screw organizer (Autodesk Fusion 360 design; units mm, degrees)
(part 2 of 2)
sketch "Sketch7" plane through (0, 0, 5) normal (0, 0, 1) x axis (-1, 0, 0)
  line L1 (-684.5, 175) -> (-500, 175)
  line L2 (-684.5, -75) -> (-684.5, 175)
  line L3 (-500, -75) -> (-684.5, -75)
  line L4 (-500, 175) -> (-500, -75)
  line L5 (-505, -70) -> (-679.5, -70)
  line L6 (-505, 170) -> (-505, -70)
  line L7 (-679.5, 170) -> (-505, 170)
  line L8 (-555.4, -70) -> (-505, -70)
  line L9 (-555.4, -38.6) -> (-555.4, -70)
  line L10 (-505, -38.6) -> (-555.4, -38.6)
  line L11 (-505, -70) -> (-505, -38.6)
  line L12 (-560.4, -70) -> (-555.4, -70)
  line L13 (-560.4, 170) -> (-560.4, -70)
  line L14 (-555.4, 170) -> (-560.4, 170)
  line L15 (-555.4, -70) -> (-555.4, 170)
  line L16 (-555.4, -38.6) -> (-505, -38.6)
  line L17 (-555.4, -30.35) -> (-555.4, -38.6)
  line L18 (-505, -30.35) -> (-555.4, -30.35)
  line L19 (-505, -38.6) -> (-505, -30.35)
  line L20 (-555.4, -30.35) -> (-505, -30.35)
  line L21 (-555.4, 6.05) -> (-555.4, -30.35)
  line L22 (-505, 6.05) -> (-555.4, 6.05)
  line L23 (-505, -30.35) -> (-505, 6.05)
  line L24 (-555.4, 6.05) -> (-505, 6.05)
  line L25 (-555.4, 14.3) -> (-555.4, 6.05)
  line L26 (-505, 14.3) -> (-555.4, 14.3)
  line L27 (-505, 6.05) -> (-505, 14.3)
  line L28 (-555.4, 14.3) -> (-505, 14.3)
  line L29 (-555.4, 55.7) -> (-555.4, 14.3)
  line L30 (-505, 55.7) -> (-555.4, 55.7)
  line L31 (-505, 14.3) -> (-505, 55.7)
  line L32 (-555.4, 55.7) -> (-505, 55.7)
  line L33 (-555.4, 63.95) -> (-555.4, 55.7)
  line L34 (-505, 63.95) -> (-555.4, 63.95)
  line L35 (-505, 55.7) -> (-505, 63.95)
  line L36 (-555.4, 63.95) -> (-505, 63.95)
  line L37 (-555.4, 110.35) -> (-555.4, 63.95)
  line L38 (-505, 110.35) -> (-555.4, 110.35)
  line L39 (-505, 63.95) -> (-505, 110.35)
  line L40 (-555.4, 170) -> (-505, 170)
  line L41 (-555.4, 118.6) -> (-555.4, 170)
  line L42 (-505, 118.6) -> (-555.4, 118.6)
  line L43 (-505, 170) -> (-505, 118.6)
  curve K1
  curve K2
  curve K3
  curve K4
  curve K5
  curve K6
  curve K7
  curve K8
  curve K9
  curve K10
  curve K11
  curve K12
  curve K13
  curve K14
  curve K15
  curve K16
  curve K17
  curve K18
  curve K19
  curve K20
  line L44 (-610.8, -70) -> (-560.4, -70)
  line L45 (-610.8, -13.6) -> (-610.8, -70)
  line L46 (-560.4, -13.6) -> (-610.8, -13.6)
  line L47 (-560.4, -70) -> (-560.4, -13.6)
  line L48 (-615.8, -70) -> (-610.8, -70)
  line L49 (-615.8, -13.6) -> (-615.8, -70)
  line L50 (-610.8, -13.6) -> (-615.8, -13.6)
  line L51 (-610.8, -70) -> (-610.8, -13.6)
  line L52 (-625.8, -13.6) -> (-560.4, -13.6)
  line L53 (-625.8, -8.6) -> (-625.8, -13.6)
  line L54 (-560.4, -8.6) -> (-625.8, -8.6)
  line L55 (-560.4, -13.6) -> (-560.4, -8.6)
  curve K21
  curve K22
  curve K23
  curve K24
  curve K25
  curve K26
  curve K27
  curve K28
  line L56 (-630.8, -13.6) -> (-625.8, -13.6)
  line L57 (-630.8, 170) -> (-630.8, -13.6)
  line L58 (-625.8, 170) -> (-630.8, 170)
  line L59 (-625.8, -13.6) -> (-625.8, 170)
  line L60 (-615.8, -13.6) -> (-630.8, -13.6)
  line L61 (-615.8, -18.6) -> (-615.8, -13.6)
  line L62 (-630.8, -18.6) -> (-615.8, -18.6)
  line L63 (-630.8, -13.6) -> (-630.8, -18.6)
  line L64 (-625.8, -8.6) -> (-560.4, -8.6)
  line L65 (-625.8, 9.8) -> (-625.8, -8.6)
  line L66 (-560.4, 9.8) -> (-625.8, 9.8)
  line L67 (-560.4, -8.6) -> (-560.4, 9.8)
  line L68 (-625.8, 9.8) -> (-560.4, 9.8)
  line L69 (-625.8, 17.44) -> (-625.8, 9.8)
  line L70 (-560.4, 17.44) -> (-625.8, 17.44)
  line L71 (-560.4, 9.8) -> (-560.4, 17.44)
  line L72 (-625.8, 17.44) -> (-560.4, 17.44)
  line L73 (-625.8, 37.84) -> (-625.8, 17.44)
  line L74 (-560.4, 37.84) -> (-625.8, 37.84)
  line L75 (-560.4, 17.44) -> (-560.4, 37.84)
  line L76 (-625.8, 37.84) -> (-560.4, 37.84)
  line L77 (-625.8, 45.48) -> (-625.8, 37.84)
  line L78 (-560.4, 45.48) -> (-625.8, 45.48)
  line L79 (-560.4, 37.84) -> (-560.4, 45.48)
  line L80 (-625.8, 45.48) -> (-560.4, 45.48)
  line L81 (-625.8, 67.88) -> (-625.8, 45.48)
  line L82 (-560.4, 67.88) -> (-625.8, 67.88)
  line L83 (-560.4, 45.48) -> (-560.4, 67.88)
  line L84 (-625.8, 67.88) -> (-560.4, 67.88)
  line L85 (-625.8, 75.52) -> (-625.8, 67.88)
  line L86 (-560.4, 75.52) -> (-625.8, 75.52)
  line L87 (-560.4, 67.88) -> (-560.4, 75.52)
  line L88 (-625.8, 75.52) -> (-560.4, 75.52)
  line L89 (-625.8, 99.92) -> (-625.8, 75.52)
  line L90 (-560.4, 99.92) -> (-625.8, 99.92)
  line L91 (-560.4, 75.52) -> (-560.4, 99.92)
  line L92 (-625.8, 99.92) -> (-560.4, 99.92)
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  point P17 (-555.4, -30.35)
  point P20 (-555.4, 6.05)
  point P23 (-555.4, 14.3)
  point P26 (-555.4, 55.7)
  point P29 (-555.4, 63.95)
  point P32 (-555.4, 110.35)
  point P35 (-555.4, 118.6)
  point P12 (-505, -38.6)
  point P21 (-505, 6.05)
  point P27 (-505, 55.7)
  point P33 (-505, 110.35)
  point P9 (-505, 170)
  point P10 (-555.4, -70)
  point P39 (-560.4, -13.6)
  point P43 (-625.8, -13.6)
  point P45 (-560.4, -8.6)
  point P47 (-630.8, 170)
  point P50 (-615.8, -18.6)
  point P53 (-625.8, 9.8)
  point P56 (-625.8, 17.44)
  point P59 (-625.8, 37.84)
  point P62 (-625.8, 45.48)
  point P65 (-625.8, 67.88)
  point P68 (-625.8, 75.52)
  point P71 (-625.8, 99.92)
  point P74 (-625.8, 107.56)
  point P77 (-625.8, 133.96)
  point P80 (-625.8, 141.6)
  point P54 (-560.4, 9.8)
  point P60 (-560.4, 37.84)
  point P66 (-560.4, 67.88)
  point P72 (-560.4, 99.92)
  point P78 (-560.4, 133.96)
  point P14 (-560.4, 170)
  point P86 (-630.8, -14.6)
  point P92 (-630.8, 40.8)
  point P82 (-649.1, -70)
  point P84 (-679.5, -19.6)
  point P88 (-646.1, -14.6)
  point P105 (-630.8, 61.85)
  point P113 (-630.8, 88.9)
  point P97 (-645.3667, 40.8)
  point P101 (-661.9333, 40.8)
  point P100 (-645.3667, 56.2)
  point P110 (-663.1, 79.125)
  point P118 (-653.1, 124.95)
  point P121 (-500, 110)
  point P125 (-684.5, 110)
  point P8 (-505, -70)
  point P13 (-560.4, -70)
  point P18 (-505, -30.35)
  point P24 (-505, 14.3)
  point P30 (-505, 63.95)
  point P36 (-505, 118.6)
  point P37 (-610.8, -70)
  point P40 (-615.8, -70)
  point P42 (-610.8, -13.6)
  point P46 (-630.8, -13.6)
  point P51 (-630.8, -18.6)
  point P57 (-560.4, 17.44)
  point P63 (-560.4, 45.48)
  point P69 (-560.4, 75.52)
  point P75 (-560.4, 107.56)
  point P81 (-560.4, 141.6)
  point P7 (-679.5, -70)
  point P87 (-679.5, -14.6)
  point P90 (-679.5, 35.8)
  point P93 (-679.5, 40.8)
  point P94 (-639.2, 40.8)
  point P96 (-630.8, 53.2)
  point P98 (-655.7667, 40.8)
  point P102 (-673.3333, 40.8)
  point P104 (-661.9333, 57.7)
  point P106 (-645.2, 61.85)
  point P108 (-630.8, 83.25)
  point P109 (-679.5, 79.125)
  point P112 (-679.5, 103.525)
  point P114 (-651.2, 88.9)
  point P116 (-630.8, 119.3)
  point P117 (-679.5, 124.95)
  point P120 (-679.5, 164.35)
  point P122 (-488, 110)
  point P124 (-500, -10)
  point P126 (-696.5, 110)
  point P128 (-684.5, -10)
  horizontal L8
  vertical L9
  horizontal L10
  vertical L11
  horizontal L12
  vertical L13
  horizontal L14
  vertical L15
  horizontal L16
  vertical L17
  horizontal L18
  vertical L19
  coincident L15 P17
  horizontal L20
  vertical L21
  horizontal L22
  vertical L23
  coincident L15 P20
  horizontal L24
  vertical L25
  horizontal L26
  vertical L27
  coincident L15 P23
  horizontal L28
  vertical L29
  horizontal L30
  vertical L31
  coincident L15 P26
  horizontal L32
  vertical L33
  horizontal L34
  vertical L35
  coincident L15 P29
  horizontal L36
  vertical L37
  horizontal L38
  vertical L39
  coincident L15 P32
  collinear L7 L14
  horizontal L40
  vertical L41
  horizontal L42
  vertical L43
  coincident L15 P35
  coincident L4
  coincident P12
  coincident L4
  coincident P21
  coincident L4
  coincident P27
  coincident L4
  coincident P33
  coincident L4
  coincident P9
  horizontal L44
  vertical L45
  horizontal L46
  vertical L47
  horizontal L48
  vertical L49
  horizontal L50
  vertical L51
  horizontal L52
  vertical L53
  horizontal L54
  vertical L55
  coincident P10
  coincident P39
  coincident P43
  coincident P45
  horizontal L56
  vertical L57
  horizontal L58
  vertical L59
  coincident L7 P47
  horizontal L60
  vertical L61
  horizontal L62
  vertical L63
  coincident L49 P50
  horizontal L64
  vertical L65
  horizontal L66
  vertical L67
  coincident L59 P53
  horizontal L68
  vertical L69
  horizontal L70
  vertical L71
  coincident L59 P56
  horizontal L72
  vertical L73
  horizontal L74
  vertical L75
  coincident L59 P59
  horizontal L76
  vertical L77
  horizontal L78
  vertical L79
  coincident L59 P62
  horizontal L80
  vertical L81
  horizontal L82
  vertical L83
  coincident L59 P65
  horizontal L84
  vertical L85
  horizontal L86
  vertical L87
  coincident L59 P68
  horizontal L88
  vertical L89
  horizontal L90
  vertical L91
  coincident L59 P71
  horizontal L92
  coincident L59 P74
  coincident L59 P77
  coincident L59 P80
  coincident L21
  coincident P54
  coincident L15
  coincident P60
  coincident L29
  coincident P66
  coincident L37
  coincident P72
  coincident L37
  coincident P78
  coincident L41
  coincident P14
  coincident L63 P86
  coincident L57 P92
  coincident L3
  coincident P82
  coincident P84
  coincident P88
  coincident L57 P105
  coincident L57 P113
  coincident P92
  coincident P97
  coincident P101
  coincident P100
  coincident P105
  coincident P110
  coincident P113
  coincident P118
  coincident L4 P121
  coincident L2 P125
  coincident L3
  coincident P8
  dimension "d349" distance P8 P10 = 50.4
  dimension "d350" distance P8 P12 = 31.4
  dimension "d351" distance P10 P13 = 5
  dimension "d352" distance P12 P18 = 8.25 (= "d354")
  dimension "d353" distance P18 P21 = 36.4
  dimension "d354" distance P21 P24 = 8.25 (= "d356")
  dimension "d355" distance P24 P27 = 41.4
  dimension "d356" distance P27 P30 = 8.25 (= "d359")
  dimension "d357" distance P30 P33 = 46.4
  dimension "d358" distance P9 P36 = 51.4
  dimension "d359" distance L38 L42 = 8.25
  dimension "d365" distance P13 P37 = 50.4
  dimension "d366" distance P13 P39 = 56.4
  dimension "d367" distance P37 P40 = 5
  dimension "d368" distance P37 P42 = 56.4
  dimension "d369" distance P39 P43 = 65.4 (= "( 13 * 5 ) * 1 mm + 0.4 mm")
  dimension "d370" distance P39 P45 = 5
  dimension "d374" distance P43 P46 = 5
  dimension "d375" distance P46 P51 = 5
  dimension "d376" distance P45 P54 = 18.4
  dimension "d377" distance P54 P57 = 7.64 (= "d379")
  dimension "d378" distance P57 P60 = 20.4
  dimension "d379" distance P60 P63 = 7.64 (= "d381")
  dimension "d380" distance P63 P66 = 22.4
  dimension "d381" distance P66 P69 = 7.64 (= "d383")
  dimension "d382" distance P69 P72 = 24.4
  dimension "d383" distance P72 P75 = 7.64 (= "d386")
  dimension "d384" distance P75 P78 = 26.4
  dimension "d385" distance P14 P81 = 28.4
  dimension "d386" distance = 7.64
  dimension "d393" distance P7 P82 = 30.4
  dimension "d394" distance P7 P84 = 50.4
  dimension "d395" distance P84 P87 = 5
  dimension "d396" distance P87 P88 = 33.4
  dimension "d397" distance P87 P90 = 50.4
  dimension "d398" distance P90 P93 = 5
  dimension "d444" distance P92 P94 = 8.4
  dimension "d445" distance P92 P96 = 12.4
  dimension "d446" distance P97 P98 = 10.4
  dimension "d447" distance P97 P100 = 15.4
  dimension "d448" distance P101 P102 = 11.4
  dimension "d449" distance P101 P104 = 16.9
  dimension "d450" distance = 6.1667 (= "d451")
  dimension "d451" distance = 6.1667 (= "d453")
  dimension "d452" distance = 15.3
  dimension "d453" distance = 6.1667
  dimension "d454" distance P105 P106 = 14.4
  dimension "d455" distance P105 P108 = 21.4
  dimension "d456" distance P109 P110 = 16.4
  dimension "d457" distance P109 P112 = 24.4
  dimension "d458" distance P113 P114 = 20.4
  dimension "d459" distance P113 P116 = 30.4
  dimension "d460" distance P117 P118 = 26.4
  dimension "d461" distance P117 P120 = 39.4
  dimension "d462" distance = 5.65 (= "d464")
  dimension "d463" distance = 5.65 (= "d462")
  dimension "d464" distance = 5.65 (= "d465")
  dimension "d465" distance = 5.65
  dimension "d466" distance = 21.425 (= "d467")
  dimension "d467" distance = 21.425
  dimension "d475" distance P121 P122 = 12
  dimension "d476" distance P121 P124 = 120
  dimension "d477" distance P125 P126 = 12
  dimension "d478" distance P125 P128 = 120
  dimension "d479" distance = 65 (= "d480")
  dimension "d480" distance = 65
  dimension "d481" distance = 65 (= "d482")
  dimension "d482" distance = 65
  dimension "d483" = -3
  dimension "d484" = 3
  dimension "d518" = -0.4
  dimension "d519" = 0.4
  dimension "d360" Text1-Height = 3
  dimension "d361" Text2-Height = 3
  dimension "d362" Text3-Height = 3
  dimension "d363" Text4-Height = 3
  dimension "d364" Text5-Height = 3
  dimension "d372" Text6-Height = 3
  dimension "d373" Text7-Height = 3
  dimension "d387" Text8-Height = 3
  dimension "d388" Text9-Height = 3
  dimension "d389" Text10-Height = 3
  dimension "d390" Text11-Height = 3
  dimension "d391" Text12-Height = 3
  dimension "d392" Text13-Height = 3
  dimension "d399" Text14-Height = 3
  dimension "d400" Text15-Height = 3
  dimension "d468" Text16-Height = 3
  dimension "d469" Text17-Height = 3
  dimension "d470" Text18-Height = 3
  dimension "d471" Text19-Height = 3
  dimension "d472" Text20-Height = 3
  dimension "d473" Text21-Height = 3
  dimension "d474" Text22-Height = 3
  dimension "d520" Text23-Height = 3
extrude "Extrude11" add sketch "Sketch5" along normal blind 40
extrude "Extrude12" cut sketch "Sketch5" along normal blind 40
extrude "Extrude13" add sketch "Sketch5" along normal blind 38
extrude "Extrude14" add sketch "Sketch5" along normal blind 45
extrude "Extrude15" add sketch "Sketch7" along normal blind 40
sketch "Sketch9" plane through (0, 0, 50) normal (0, 0, 1) x axis (-1, 0, 0)
  line L1 (-188.8937, -5.7642) -> (-188.8937, 109.0358)
  line L2 (-195.6937, -5.7642) -> (-188.8937, -5.7642)
  line L3 (-195.6937, 109.0358) -> (-195.6937, -5.7642)
  line L4 (-188.8937, 109.0358) -> (-195.6937, 109.0358)
  line L5 (-186.2937, -8.3642) -> (-198.2937, -8.3642)
  line L6 (-186.2937, 111.6358) -> (-186.2937, -8.3642)
  line L7 (-198.2937, 111.6358) -> (-186.2937, 111.6358)
  line L8 (-198.2937, -8.3642) -> (-198.2937, 111.6358)
  line L9 (-195.2937, 108.6358) -> (-195.2937, -5.3642)
  line L10 (-189.2937, 108.6358) -> (-195.2937, 108.6358)
  line L11 (-189.2937, -5.3642) -> (-189.2937, 108.6358)
  line L12 (-195.2937, -5.3642) -> (-189.2937, -5.3642)
  line L13 (-392.1937, -5.7642) -> (-385.3937, -5.7642)
  line L14 (-392.1937, 109.0358) -> (-392.1937, -5.7642)
  line L15 (-385.3937, 109.0358) -> (-392.1937, 109.0358)
  line L16 (-385.3937, -5.7642) -> (-385.3937, 109.0358)
  line L17 (-382.7937, 111.6358) -> (-382.7937, -8.3642)
  line L18 (-394.7937, 111.6358) -> (-382.7937, 111.6358)
  line L19 (-394.7937, -8.3642) -> (-394.7937, 111.6358)
  line L20 (-382.7937, -8.3642) -> (-394.7937, -8.3642)
  line L21 (-391.7937, 108.6358) -> (-391.7937, -5.3642)
  line L22 (-385.7937, 108.6358) -> (-391.7937, 108.6358)
  line L23 (-385.7937, -5.3642) -> (-385.7937, 108.6358)
  line L24 (-391.7937, -5.3642) -> (-385.7937, -5.3642)
  dimension "d508" = 0.4
  dimension "d509" = 0.4
extrude "Extrude18" add sketch "Sketch9" profile of L1 L2 L3 L4 L10 L9 L11 L12 L13 L14 L15 L16 L22 L23 L21 L24 against normal blind 25
extrude "Extrude19" add sketch "Sketch9" profile of L10 L9 L11 L12 L22 L23 L21 L24 along normal blind 20
extrude "Extrude20" cut sketch "Sketch7" along normal blind 40
extrude "Extrude21" add sketch "Sketch7" along normal blind 38
extrude "Extrude22" add sketch "Sketch7" along normal blind 45
sketch "Sketch10" plane through (0, 0, 50) normal (0, 0, 1) x axis (-1, 0, 0)
  line L1 (-490.6, -7.4) -> (-490.6, 107.4)
  line L2 (-497.4, -7.4) -> (-490.6, -7.4)
  line L3 (-497.4, 107.4) -> (-497.4, -7.4)
  line L4 (-490.6, 107.4) -> (-497.4, 107.4)
  line L5 (-488, -10) -> (-500, -10)
  line L6 (-488, 110) -> (-488, -10)
  line L7 (-500, 110) -> (-488, 110)
  line L8 (-500, -10) -> (-500, 110)
  line L9 (-497, 107) -> (-497, -7)
  line L10 (-491, 107) -> (-497, 107)
  line L11 (-491, -7) -> (-491, 107)
  line L12 (-497, -7) -> (-491, -7)
  line L13 (-693.9, -7.4) -> (-687.1, -7.4)
  line L14 (-693.9, 107.4) -> (-693.9, -7.4)
  line L15 (-687.1, 107.4) -> (-693.9, 107.4)
  line L16 (-687.1, -7.4) -> (-687.1, 107.4)
  line L17 (-684.5, 110) -> (-684.5, -10)
  line L18 (-696.5, 110) -> (-684.5, 110)
  line L19 (-696.5, -10) -> (-696.5, 110)
  line L20 (-684.5, -10) -> (-696.5, -10)
  line L21 (-687.5, -7) -> (-687.5, 107)
  line L22 (-693.5, -7) -> (-687.5, -7)
  line L23 (-693.5, 107) -> (-693.5, -7)
  line L24 (-687.5, 107) -> (-693.5, 107)
  dimension "d523" = 0.4
  dimension "d524" = 0.4
extrude "Extrude23" add sketch "Sketch10" profile of L1 L2 L3 L4 L9 L11 L12 L10 L13 L14 L15 L16 L23 L22 L21 L24 against normal blind 25
extrude "Extrude24" add sketch "Sketch10" profile of L9 L11 L12 L10 L23 L22 L21 L24 along normal blind 5
fillet "Fillet3" radius 3
fillet "Fillet4" radius 2
sketch "Sketch11" plane through (0, 0, 0) normal (0, 0, 1) x axis (1, 0, 0)
  line L1 (932.4779, 67.6864) -> (747.9779, 67.6864)
  line L2 (932.4779, -182.3136) -> (932.4779, 67.6864)
  line L3 (747.9779, -182.3136) -> (932.4779, -182.3136)
  line L4 (747.9779, 67.6864) -> (747.9779, -182.3136)
  line L5 (944.4779, 2.6864) -> (932.4779, 2.6864)
  line L6 (944.4779, -117.3136) -> (944.4779, 2.6864)
  line L7 (932.4779, -117.3136) -> (944.4779, -117.3136)
  line L8 (932.4779, 2.6864) -> (932.4779, -117.3136)
  line L9 (735.9779, -117.3136) -> (747.9779, -117.3136)
  line L10 (735.9779, 2.6864) -> (735.9779, -117.3136)
  line L11 (747.9779, 2.6864) -> (735.9779, 2.6864)
  line L12 (747.9779, -117.3136) -> (747.9779, 2.6864)
  line L13 (747.9779, -129.3136) -> (735.9779, -117.3136)
  line L14 (752.9484, -117.3136) -> (735.9779, -117.3136)
  line L15 (747.9779, 14.6864) -> (735.9779, 2.6864)
  line L16 (752.9484, 2.6864) -> (735.9779, 2.6864)
  line L17 (932.4779, 14.6864) -> (944.4779, 2.6864)
  line L18 (961.4484, 2.6864) -> (944.4779, 2.6864)
  line L19 (932.4779, -129.3136) -> (944.4779, -117.3136)
  line L20 (961.4484, -117.3136) -> (944.4779, -117.3136)
  line L21 (744.9779, -0.3136) -> (738.9779, -0.3136)
  line L22 (744.9779, -114.3136) -> (744.9779, -0.3136)
  line L23 (738.9779, -114.3136) -> (744.9779, -114.3136)
  line L24 (738.9779, -0.3136) -> (738.9779, -114.3136)
  line L25 (935.4779, -114.3136) -> (941.4779, -114.3136)
  line L26 (935.4779, -0.3136) -> (935.4779, -114.3136)
  line L27 (941.4779, -0.3136) -> (935.4779, -0.3136)
  line L28 (941.4779, -114.3136) -> (941.4779, -0.3136)
  point P6 (932.4779, 2.6864)
  point P10 (747.9779, -117.3136)
  point P14 (747.9779, -129.3136)
  point P16 (747.9779, 14.6864)
  point P18 (932.4779, 14.6864)
  point P20 (932.4779, -129.3136)
  point P2 (747.9779, 67.6864)
  point P3 (932.4779, 67.6864)
  point P5 (747.9779, -182.3136)
  point P7 (944.4779, 2.6864)
  point P9 (932.4779, -117.3136)
  point P11 (735.9779, -117.3136)
  point P13 (747.9779, 2.6864)
  point P4 (932.4779, -182.3136)
  horizontal L1
  vertical L2
  horizontal L3
  vertical L4
  horizontal L5
  vertical L6
  horizontal L7
  vertical L8
  coincident L2 P6
  horizontal L9
  vertical L10
  horizontal L11
  vertical L12
  coincident L4 P10
  horizontal L14
  coincident L4 P14
  horizontal L16
  coincident L4 P16
  horizontal L18
  coincident L2 P18
  horizontal L20
  coincident L2 P20
  dimension "d533" distance P2 P3 = 184.5
  dimension "d534" distance P2 P5 = 250
  dimension "d535" distance P6 P7 = 12
  dimension "d536" distance P6 P9 = 120
  dimension "d537" distance P10 P11 = 12
  dimension "d538" distance P10 P13 = 120
  dimension "d539" distance P5 L9 = 65 (= "d540")
  dimension "d540" distance P2 L11 = 65
  dimension "d541" distance P4 L7 = 65 (= "d542")
  dimension "d542" distance P3 L5 = 65
  dimension "d543" angle L13 L14 = 45
  dimension "d544" angle L15 L16 = 45
  dimension "d545" angle L17 L18 = 135
  dimension "d546" angle L19 L20 = 135
  dimension "d553" = 3
  dimension "d554" = 3
extrude "Extrude25" new body sketch "Sketch11" profile of L1 L2 L3 L4 L8 L12 distance -5
extrude "Extrude26" add sketch "Sketch11" profile of L2 L4 L5 L6 L7 L8 L9 L10 L11 L12 L13 L15 L17 L19 L24 L21 L22 L23 L26 L25 L28 L27 along normal blind 5
fillet "Fillet5" radius 3
sketch "Sketch12" plane through (0, 0, 5) normal (0, 0, 1) x axis (-1, 0, 0)
  line L1 (-941.4779, 0.3136) -> (-935.4779, 0.3136)
  line L2 (-941.4779, 114.3136) -> (-941.4779, 0.3136)
  line L3 (-935.4779, 114.3136) -> (-941.4779, 114.3136)
  line L4 (-935.4779, 0.3136) -> (-935.4779, 114.3136)
  line L5 (-738.9779, 114.3136) -> (-744.9779, 114.3136)
  line L6 (-738.9779, 0.3136) -> (-738.9779, 114.3136)
  line L7 (-744.9779, 0.3136) -> (-738.9779, 0.3136)
  line L8 (-744.9779, 114.3136) -> (-744.9779, 0.3136)
  line L9 (-735.9779, 116.0709) -> (-735.9779, -1.4438)
  line L10 (-747.9779, 129.3136) -> (-736.8566, 118.1923)
  line L11 (-747.9779, 179.3136) -> (-747.9779, 129.3136)
  line L12 (-929.4779, 182.3136) -> (-750.9779, 182.3136)
  line L13 (-932.4779, 129.3136) -> (-932.4779, 179.3136)
  line L14 (-943.5992, 118.1923) -> (-932.4779, 129.3136)
  line L15 (-944.4779, -1.4438) -> (-944.4779, 116.0709)
  line L16 (-932.4779, -14.6864) -> (-943.5992, -3.5651)
  line L17 (-932.4779, -64.6864) -> (-932.4779, -14.6864)
  line L18 (-750.9779, -67.6864) -> (-929.4779, -67.6864)
  line L19 (-747.9779, -14.6864) -> (-747.9779, -64.6864)
  line L20 (-736.8566, -3.5651) -> (-747.9779, -14.6864)
  line L21 (-808.3534, 138.5187) -> (-782.7283, 122.9189)
  line L22 (-870.7527, 36.0184) -> (-808.3534, 138.5187)
  line L23 (-845.1276, 20.4185) -> (-870.7527, 36.0184)
  line L24 (-782.7283, 122.9189) -> (-845.1276, 20.4185)
  line L25 (-891.2528, 48.4982) -> (-824.6275, 7.9387)
  line L26 (-906.8526, 22.8731) -> (-891.2528, 48.4982)
  line L27 (-840.2274, -17.6864) -> (-906.8526, 22.8731)
  line L28 (-824.6275, 7.9387) -> (-840.2274, -17.6864)
  curve K1 (-840.2279, 170.0636) -> (-840.2279, -55.4364)
  curve K2 (-920.2279, 57.3136) -> (-760.2279, 57.3136)
  line L29 (-932.4779, 182.3136) -> (-932.4779, -67.6864)
  line L30 (-747.9779, -67.6864) -> (-747.9779, 182.3136)
  line L31 (-747.9779, 182.3136) -> (-932.4779, 182.3136)
  line L32 (-932.4779, -67.6864) -> (-747.9779, -67.6864)
  line L33 (-826.9278, 50.3145) -> (-845.1276, 20.4185)
  line L34 (-893.094, 120) -> (-881.547, 140)
  line L35 (-881.547, 100) -> (-893.094, 120)
  line L36 (-858.453, 100) -> (-881.547, 100)
  line L37 (-846.906, 120) -> (-858.453, 100)
  line L38 (-858.453, 140) -> (-846.906, 120)
  line L39 (-881.547, 140) -> (-858.453, 140)
  arc A1 centre (-738.9779, -1.4438) radius 3 clockwise from (-735.9779, -1.4438) to (-736.8566, -3.5651)
  arc A2 centre (-738.9779, 116.0709) radius 3 clockwise from (-736.8566, 118.1923) to (-735.9779, 116.0709)
  arc A3 centre (-750.9779, 179.3136) radius 3 clockwise from (-750.9779, 182.3136) to (-747.9779, 179.3136)
  arc A4 centre (-929.4779, 179.3136) radius 3 clockwise from (-932.4779, 179.3136) to (-929.4779, 182.3136)
  arc A5 centre (-941.4779, 116.0709) radius 3 clockwise from (-944.4779, 116.0709) to (-943.5992, 118.1923)
  arc A6 centre (-941.4779, -1.4438) radius 3 clockwise from (-943.5992, -3.5651) to (-944.4779, -1.4438)
  arc A7 centre (-929.4779, -64.6864) radius 3 clockwise from (-929.4779, -67.6864) to (-932.4779, -64.6864)
  arc A8 centre (-750.9779, -64.6864) radius 3 clockwise from (-747.9779, -64.6864) to (-750.9779, -67.6864)
  closed curve K3 centre (-840.2279, 57.3136)
  circle C1 centre (-840.2279, 57.3136) radius 92.25
  arc A9 centre (-820.2706, 107.7249) radius 57.7951 clockwise from (-826.9278, 50.3145) to (-855.1529, 61.6434)
  arc A10 centre (-816.8706, 113.3099) radius 57.7951 clockwise from (-823.5279, 55.8994) to (-851.7529, 67.2284)
  arc A11 centre (-813.4706, 118.8948) radius 57.7951 clockwise from (-820.1279, 61.4844) to (-848.353, 72.8134)
  arc A12 centre (-810.0707, 124.4798) radius 57.7951 clockwise from (-816.7279, 67.0693) to (-844.953, 78.3983)
  arc A13 centre (-806.6707, 130.0647) radius 57.7951 clockwise from (-813.328, 72.6543) to (-841.553, 83.9833)
  arc A14 centre (-803.2708, 135.6497) radius 57.7951 clockwise from (-809.928, 78.2393) to (-838.1531, 89.5682)
  arc A15 centre (-799.8708, 141.2346) radius 57.7951 clockwise from (-806.528, 83.8242) to (-834.7531, 95.1532)
  arc A16 centre (-796.4708, 146.8196) radius 57.7951 clockwise from (-803.1281, 89.4092) to (-831.3532, 100.7381)
  arc A17 centre (-793.0709, 152.4046) radius 57.7951 clockwise from (-799.7281, 94.9941) to (-827.9532, 106.3231)
  arc A18 centre (-789.6709, 157.9895) radius 57.7951 clockwise from (-796.3282, 100.5791) to (-824.5532, 111.9081)
  arc A19 centre (-786.2709, 163.5745) radius 57.7951 clockwise from (-792.9282, 106.164) to (-821.1533, 117.493)
  arc A20 centre (-782.871, 169.1594) radius 57.7951 clockwise from (-789.5282, 111.749) to (-817.7533, 123.078)
  arc A21 centre (-779.471, 174.7444) radius 57.7951 clockwise from (-786.1283, 117.3339) to (-814.3533, 128.6629)
  arc A22 centre (-776.0711, 180.3293) radius 57.7951 clockwise from (-782.7283, 122.9189) to (-810.9534, 134.2479)
  arc A23 centre (-820.5553, 107.8982) radius 59.7537 clockwise from (-827.9678, 48.6061) to (-856.1929, 59.9351)
  arc A24 centre (-817.1553, 113.4832) radius 59.7537 clockwise from (-824.5678, 54.1911) to (-852.7929, 65.5201)
  arc A25 centre (-813.7554, 119.0682) radius 59.7537 clockwise from (-821.1679, 59.776) to (-849.3929, 71.105)
  arc A26 centre (-810.3554, 124.6531) radius 59.7537 clockwise from (-817.7679, 65.361) to (-845.993, 76.69)
  arc A27 centre (-806.9554, 130.2381) radius 59.7537 clockwise from (-814.368, 70.946) to (-842.593, 82.2749)
  arc A28 centre (-803.5555, 135.823) radius 59.7537 clockwise from (-810.968, 76.5309) to (-839.1931, 87.8599)
  arc A29 centre (-800.1555, 141.408) radius 59.7537 clockwise from (-807.568, 82.1159) to (-835.7931, 93.4448)
  arc A30 centre (-796.7556, 146.9929) radius 59.7537 clockwise from (-804.1681, 87.7008) to (-832.3931, 99.0298)
  arc A31 centre (-793.3556, 152.5779) radius 59.7537 clockwise from (-800.7681, 93.2858) to (-828.9932, 104.6148)
  arc A32 centre (-789.9556, 158.1628) radius 59.7537 clockwise from (-797.3681, 98.8707) to (-825.5932, 110.1997)
  arc A33 centre (-786.5557, 163.7478) radius 59.7537 clockwise from (-793.9682, 104.4557) to (-822.1933, 115.7847)
  arc A34 centre (-783.1557, 169.3328) radius 59.7537 clockwise from (-790.5682, 110.0406) to (-818.7933, 121.3696)
  arc A35 centre (-779.7557, 174.9177) radius 59.7537 clockwise from (-787.1683, 115.6256) to (-815.3933, 126.9546)
  arc A36 centre (-776.3558, 180.5027) radius 59.7537 clockwise from (-783.7683, 121.2106) to (-811.9934, 132.5395)
  circle C2 centre (-795, 25) radius 20
  circle C3 centre (-795, 25) radius 5
  circle C4 centre (-870, 120) radius 5
  point P47 (-840.2279, -55.4364)
  point P48 (-840.2279, 170.0636)
  point P49 (-760.2279, 57.3136)
  point P50 (-920.2279, 57.3136)
  point P56 (-826.9278, 50.3145)
  point P57 (-855.1529, 61.6434)
  point P98 (-827.9678, 48.6061)
  point P99 (-856.1929, 59.9351)
  point P101 (-856.1929, 59.9351)
  point P100 (-827.9678, 48.6061)
  point P150 (-870, 120)
  point P151 (-870, 120)
  point P38 (-782.7283, 122.9189)
  point P41 (-845.1276, 20.4185)
  point P42 (-824.6275, 7.9387)
  point P45 (-840.2274, -17.6864)
  point P43 (-891.2528, 48.4982)
  point P39 (-808.3534, 138.5187)
  point P44 (-906.8526, 22.8731)
  point P46 (-840.2279, 57.3136)
  point P55 (-840.2279, 57.3136)
  point P58 (-820.2706, 107.7249)
  point P40 (-870.7527, 36.0184)
  point P102 (-820.5553, 107.8982)
  perpendicular L21 L22
  parallel L21 L23
  parallel L22 L24
  perpendicular L25 L26
  parallel L25 L27
  parallel L26 L28
  perpendicular L22 L25
  collinear L23 L25
  coincident K3 P47
  coincident K3 P48
  coincident K3 P49
  coincident K3 P50
  parallel L8 K1
  concentric K3 C1
  tangent L30 C1
  coincident L24 P56
  coincident L22 P57
  coincident L33 P98
  coincident L22 P99
  coincident P99 P101
  coincident P98 P100
  concentric C2 C3
  coincident P150 P151
  dimension "d555" distance P38 P41 = 120 (= "d556 * 4")
  dimension "d556" distance P42 P45 = 30
  dimension "d557" distance L24 P42 = 24 (= "d556 * 0.8")
  dimension "d558" distance L22 P43 = 24 (= "d557")
  dimension "d559" distance P38 P39 = 30
  dimension "d560" distance P44 P45 = 78
  dimension "d561" distance P43 P44 = 30
  dimension "d562" distance P46 L29 = 92.25 (= "d563")
  dimension "d563" distance P46 L30 = 92.25
  dimension "d564" distance P48 L31 = 12.25 (= "d565")
  dimension "d565" distance P47 L32 = 12.25 (= "d563 - d568")
  dimension "d566" distance P46 P48 = 112.75
  dimension "d567" distance P46 P47 = 112.75
  dimension "d568" distance P46 P50 = 80
  dimension "d569" distance P46 P49 = 80
  dimension "d570" distance P45 P55 = 75
  dimension "d571" distance P44 P55 = 75 (= "d570")
  dimension "d572" distance P38 P55 = 87.2368 (= "d573")
  dimension "d573" distance P39 P55 = 87.2368
  dimension "d574" distance P41 P56 = 35
  dimension "d581" distance L25 P58 = 87.5 (= "d574 * 2.5")
  dimension "d582" distance P40 P57 = 30
  dimension "d587" distance P40 P99 = 28 (= "d582 - 2 mm")
  dimension "d588" distance P41 P98 = 33 (= "d574 - 2 mm")
  dimension "d589" distance L25 P102 = 87.5 (= "d581")
  dimension "d596" = 4
  dimension "d599" diameter C2 = 40
  dimension "d600" diameter C3 = 10
  dimension "d601" distance P150 L39 = 20
  dimension "d602" diameter C4 = 10
  dimension "d585" R-Pattern1-uDistance = 85
  dimension "d586" R-Pattern1-vDistance = 0
  dimension "d592" R-Pattern2-uDistance = 85
  dimension "d593" R-Pattern2-vDistance = 0
extrude "Extrude27" cut sketch "Sketch12" profile of L21 L22 L23 L24 L25 L33 A9 A10 A11 A12 A13 A14 A15 A16 A17 A18 A19 A20 A21 A22 A23 A24 A25 A26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 against normal blind 2.5
extrude "Extrude28" cut sketch "Sketch12" profile of L23 L25 L26 L27 L28 K3 L34 L35 L36 L37 L38 L39 C4 against normal blind 5
remove_body "RemoveBody1"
